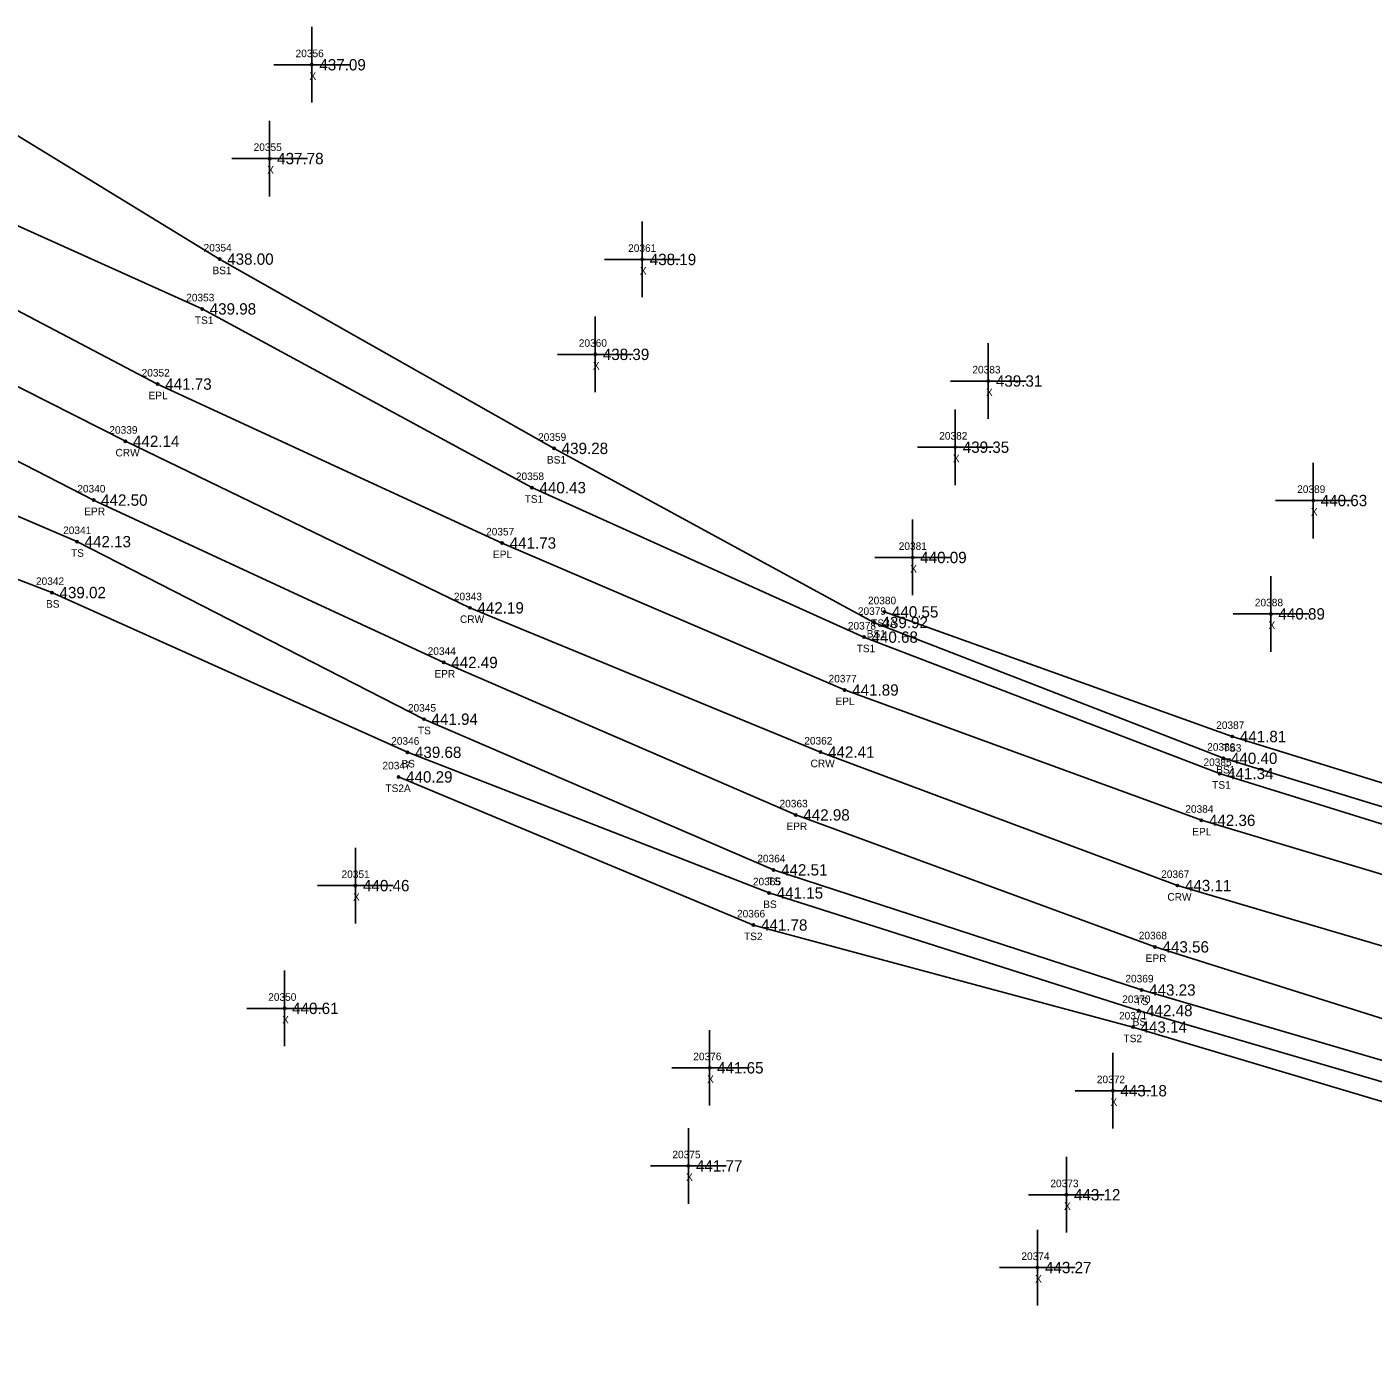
# Model space of a CAD drawing. Extents: x 1810114 to 1811498, y 790790 to 791824.
# Drawn here: x 1810834.7 to 1811012.6, y 791129.6 to 791306.9 of the extents above; entities that cross this region are included whole.
import ezdxf

# ---------------------------------------------------------------- set-up
doc = ezdxf.new("R2010")
doc.units = 0
for name, color, linetype in [('RD_DTM_BkLn1', 7, 'Continuous'), ('RD_DTM_BkLn2', 7, 'Continuous'), ('RD_DTM_BkLn_txCode', 7, 'Continuous'), ('RD_EX_Misc', 7, 'Continuous'), ('RD_EX_Misc_txCode', 7, 'Continuous'), ('RD_EX_Road', 7, 'Continuous'), ('RD_EX_Road_txCode', 7, 'Continuous'), ('RD_EX_TX_Misc_ELEV', 7, 'Continuous'), ('RD_EX_TX_Road_ELEV', 7, 'Continuous'), ('RD_HC_Survey_ELEV', 7, 'Continuous'), ('RD_HC_Survey_txCode', 7, 'Continuous'), ('RD_SMD_Locator', 7, 'Continuous')]:
    doc.layers.add(name, color=color, linetype=linetype)

msp = doc.modelspace()

# ---------------------------------------------------------------- linework, layer by layer
at = {"layer": 'RD_DTM_BkLn1'}
msp.add_lwpolyline([(1810803.51, 791274.51), (1810847.74, 791252.12), (1810893.26, 791230.1), (1810939.59, 791211.03), (1810986.75, 791193.39), (1811034.36, 791179.34), (1811083.17, 791167.31), (1811132.79, 791157.79), (1811182.67, 791151.51), (1811232.87, 791147.29), (1811282.59, 791145.39), (1811332.65, 791144.69), (1811383.13, 791143.44), (1811433.19, 791141.72), (1811483.07, 791139)], dxfattribs=at)
at = {"layer": 'RD_DTM_BkLn2'}
for points in [[(1810797.71, 791296.87), (1810806.65, 791301.43), (1810818.39, 791301.77), (1810860.19, 791276.21), (1810904.39, 791251.18), (1810946.65, 791228.17), (1810992.83, 791210.21), (1811039.32, 791196), (1811086.62, 791185.05), (1811136.39, 791175.32), (1811184.54, 791168.49), (1811233.77, 791164.27), (1811283.33, 791162.64), (1811288.69, 791162.37)], [(1810810.94, 791288.35), (1810813.31, 791289.84), (1810816.6, 791289.48), (1810819.25, 791288.81), (1810826.35, 791283.83), (1810857.88, 791269.62), (1810901.46, 791245.99), (1810945.33, 791226.23), (1810992.32, 791208.19), (1811038.63, 791193.8), (1811085.97, 791182.59), (1811135.79, 791172.72), (1811184.32, 791165.75), (1811233.45, 791162.61), (1811282.83, 791159.28), (1811288.11, 791158.81), (1811290.26, 791160.7), (1811291.15, 791162.18)], [(1810798.82, 791261.28), (1810799.43, 791259.17), (1810802.84, 791255.6), (1810808.45, 791252.93), (1810841.34, 791238.85), (1810887.19, 791215.38), (1810933.38, 791195.46), (1810982.02, 791179.58), (1811030.36, 791165.41), (1811080.28, 791153.78), (1811130.64, 791143.41), (1811141.73, 791142.21), (1811149.36, 791140.89), (1811151.79, 791139.84), (1811152.74, 791137.29)], [(1810783.34, 791255.23), (1810786.99, 791254.41), (1810790.75, 791251.26), (1810797.13, 791248.85), (1810804.71, 791244.89), (1810838.03, 791232.12), (1810885, 791211), (1810932.8, 791192.41), (1810981.62, 791176.86), (1811029.91, 791162.73), (1811079.91, 791150.39), (1811130.24, 791140.14), (1811146.59, 791138.06), (1811151.52, 791137.46)], [(1810948.03, 791229.57), (1810994, 791213.09), (1811040.42, 791198.74), (1811088.11, 791189.61), (1811135.95, 791180.55), (1811184.97, 791175.18), (1811234.87, 791170.81), (1811283.91, 791165.94), (1811289.01, 791164.74), (1811290.58, 791163.58), (1811291.15, 791162.18)], [(1810883.83, 791207.75), (1810930.73, 791188.17), (1810980.88, 791174.68), (1811028.83, 791160.33), (1811078.75, 791145.78), (1811129.26, 791134.04), (1811143.61, 791131.25), (1811148.31, 791132.87), (1811151.39, 791134.37), (1811152.74, 791137.29)]]:
    msp.add_lwpolyline(points, dxfattribs=at)
at = {"layer": 'RD_EX_Misc'}
for p, q in [((1810872.37, 791296.9), (1810872.37, 791306.9)), ((1810867.37, 791301.9), (1810877.37, 791301.9)), ((1810866.79, 791284.5), (1810866.79, 791294.5)), ((1810861.79, 791289.5), (1810871.79, 791289.5)), ((1810916.03, 791271.16), (1810916.03, 791281.16)), ((1810911.03, 791276.16), (1810921.03, 791276.16)), ((1810909.83, 791258.61), (1810909.83, 791268.61)), ((1810961.77, 791255.09), (1810961.77, 791265.09)), ((1810904.83, 791263.61), (1810914.83, 791263.61)), ((1810956.77, 791260.09), (1810966.77, 791260.09)), ((1810957.39, 791246.34), (1810957.39, 791256.34)), ((1810952.39, 791251.34), (1810962.39, 791251.34)), ((1811004.7, 791239.29), (1811004.7, 791249.29)), ((1810999.7, 791244.29), (1811009.7, 791244.29)), ((1810951.77, 791231.76), (1810951.77, 791241.76)), ((1810946.77, 791236.76), (1810956.77, 791236.76)), ((1810999.11, 791224.3), (1810999.11, 791234.3)), ((1810994.11, 791229.3), (1811004.11, 791229.3)), ((1810878.14, 791188.38), (1810878.14, 791198.38)), ((1810873.14, 791193.38), (1810883.14, 791193.38)), ((1810868.77, 791172.15), (1810868.77, 791182.15)), ((1810863.77, 791177.15), (1810873.77, 791177.15)), ((1810924.93, 791164.29), (1810924.93, 791174.29)), ((1810978.23, 791161.26), (1810978.23, 791171.26)), ((1810919.93, 791169.29), (1810929.93, 791169.29)), ((1810973.23, 791166.26), (1810983.23, 791166.26)), ((1810922.14, 791151.33), (1810922.14, 791161.33)), ((1810972.09, 791147.51), (1810972.09, 791157.51)), ((1810917.14, 791156.33), (1810927.14, 791156.33)), ((1810967.09, 791152.51), (1810977.09, 791152.51)), ((1810968.26, 791137.89), (1810968.26, 791147.89)), ((1810963.26, 791142.89), (1810973.26, 791142.89))]:
    msp.add_line(p, q, dxfattribs=at)
at = {"layer": 'RD_EX_Road'}
for points in [[(1810807.88, 791282.84), (1810852, 791259.68), (1810897.52, 791238.67), (1810942.78, 791219.24), (1810989.92, 791202.01), (1811037.03, 791187.9), (1811084.94, 791176.28), (1811134.78, 791167.28), (1811183.92, 791161.02), (1811232.9, 791156.58), (1811282.68, 791154.92), (1811285.25, 791154.67), (1811313.54, 791153.96), (1811332.83, 791153.68), (1811383.78, 791152.53), (1811433.81, 791151.61), (1811483.97, 791148.18)], [(1810799.46, 791266.97), (1810843.53, 791244.35), (1810889.8, 791222.88), (1810936.32, 791202.72), (1810983.79, 791185.28), (1811031.51, 791170.21), (1811081.62, 791158.02), (1811131.99, 791148.92), (1811148.3, 791146.24), (1811177.02, 791142.75), (1811182.52, 791142.23), (1811232.71, 791137.62), (1811281.86, 791136.25), (1811332.25, 791135.72), (1811383.92, 791134.19), (1811422.24, 791132.82), (1811433.21, 791132.2), (1811452.43, 791131.25), (1811482.29, 791129.59)]]:
    msp.add_lwpolyline(points, dxfattribs=at)
at = {"layer": 'RD_SMD_Locator'}
for centre in [(1810872.37, 791301.9), (1810866.79, 791289.5), (1810860.19, 791276.21), (1810916.03, 791276.16), (1810857.88, 791269.62), (1810909.83, 791263.61), (1810852, 791259.68), (1810961.77, 791260.09), (1810847.74, 791252.12), (1810904.39, 791251.18), (1810957.39, 791251.34), (1810901.46, 791245.99), (1810843.53, 791244.35), (1811004.7, 791244.29), (1810841.34, 791238.85), (1810897.52, 791238.67), (1810951.77, 791236.76), (1810838.03, 791232.12), (1810893.26, 791230.1), (1810948.03, 791229.57), (1810999.11, 791229.3), (1810946.65, 791228.17), (1810945.33, 791226.23), (1810889.8, 791222.88), (1810942.78, 791219.24), (1810887.19, 791215.38), (1810994, 791213.09), (1810885, 791211), (1810939.59, 791211.03), (1810992.83, 791210.21), (1810883.83, 791207.75), (1810992.32, 791208.19), (1810936.32, 791202.72), (1810989.92, 791202.01), (1810933.38, 791195.46), (1810878.14, 791193.38), (1810986.75, 791193.39), (1810932.8, 791192.41), (1810930.73, 791188.17), (1810983.79, 791185.28), (1810982.02, 791179.58), (1810868.77, 791177.15), (1810981.62, 791176.86), (1810980.88, 791174.68), (1810924.93, 791169.29), (1810978.23, 791166.26), (1810922.14, 791156.33), (1810972.09, 791152.51), (1810968.26, 791142.89)]:
    msp.add_circle(centre, 0.15, dxfattribs=at)

# ---------------------------------------------------------------- texts
at = {"layer": 'RD_DTM_BkLn_txCode'}
for s, p in [('20354', (1810858.07, 791277.21)), ('BS1', (1810859.24, 791274.21)), ('20353', (1810855.77, 791270.62)), ('TS1', (1810856.92, 791267.62)), ('20359', (1810902.27, 791252.18)), ('BS1', (1810903.44, 791249.18)), ('20358', (1810899.34, 791246.99)), ('TS1', (1810900.5, 791243.99)), ('20341', (1810839.51, 791239.85)), ('TS', (1810840.55, 791236.85)), ('20342', (1810835.92, 791233.12)), ('BS', (1810837.25, 791230.12)), ('20380', (1810945.87, 791230.57)), ('20379', (1810944.53, 791229.17)), ('20378', (1810943.21, 791227.23)), ('BS1', (1810945.7, 791226.17)), ('TS3A', (1810946.29, 791227.57)), ('TS1', (1810944.37, 791224.23)), ('20345', (1810885.07, 791216.38)), ('TS', (1810886.39, 791213.38)), ('20387', (1810991.88, 791214.09)), ('20346', (1810882.86, 791212)), ('20386', (1810990.69, 791211.21)), ('TS3', (1810992.76, 791211.09)), ('20347', (1810881.71, 791208.75)), ('BS', (1810884.22, 791209)), ('20385', (1810990.2, 791209.19)), ('BS1', (1810991.88, 791208.21)), ('TS2A', (1810882.1, 791205.75)), ('TS1', (1810991.35, 791206.19)), ('20364', (1810931.24, 791196.46)), ('20365', (1810930.66, 791193.41)), ('TS', (1810932.59, 791193.46)), ('BS', (1810932.02, 791190.41)), ('20366', (1810928.56, 791189.17)), ('TS2', (1810929.48, 791186.17)), ('20369', (1810979.88, 791180.58)), ('20370', (1810979.47, 791177.86)), ('TS', (1810981.23, 791177.58)), ('20371', (1810979.04, 791175.68)), ('BS', (1810980.84, 791174.86)), ('TS2', (1810979.63, 791172.68))]:
    msp.add_text(s, height=1, dxfattribs=at).set_placement(p)
at = {"layer": 'RD_EX_Misc_txCode'}
for s, p in [('20356', (1810870.23, 791302.9)), ('X', (1810872.06, 791299.9)), ('20355', (1810864.68, 791290.5)), ('X', (1810866.48, 791287.5)), ('20361', (1810914.17, 791277.16)), ('X', (1810915.72, 791274.16)), ('20360', (1810907.65, 791264.61)), ('X', (1810909.51, 791261.61)), ('20383', (1810959.66, 791261.09)), ('X', (1810961.46, 791258.09)), ('20382', (1810955.28, 791252.34)), ('X', (1810957.08, 791249.34)), ('20389', (1811002.58, 791245.29)), ('X', (1811004.39, 791242.29)), ('20381', (1810949.93, 791237.76)), ('X', (1810951.45, 791234.76)), ('20388', (1810996.99, 791230.3)), ('X', (1810998.79, 791227.3)), ('20351', (1810876.3, 791194.38)), ('X', (1810877.82, 791191.38)), ('20350', (1810866.61, 791178.15)), ('X', (1810868.45, 791175.15)), ('20376', (1810922.78, 791170.29)), ('X', (1810924.61, 791167.29)), ('20372', (1810976.11, 791167.26)), ('X', (1810977.91, 791164.26)), ('20375', (1810920.02, 791157.33)), ('X', (1810921.83, 791154.33)), ('20373', (1810969.97, 791153.51)), ('X', (1810971.77, 791150.51)), ('20374', (1810966.14, 791143.89)), ('X', (1810967.95, 791140.89))]:
    msp.add_text(s, height=1, dxfattribs=at).set_placement(p)
at = {"layer": 'RD_EX_Road_txCode'}
for s, p in [('20352', (1810849.88, 791260.68)), ('EPL', (1810850.8, 791257.68)), ('20340', (1810841.38, 791245.35)), ('EPR', (1810842.3, 791242.35)), ('20357', (1810895.4, 791239.67)), ('EPL', (1810896.31, 791236.67)), ('20344', (1810887.68, 791223.88)), ('EPR', (1810888.57, 791220.88)), ('20377', (1810940.66, 791220.24)), ('EPL', (1810941.57, 791217.24)), ('20363', (1810934.18, 791203.72)), ('20384', (1810987.8, 791203.01)), ('EPR', (1810935.09, 791200.72)), ('EPL', (1810988.72, 791200.01)), ('20368', (1810981.65, 791186.28)), ('EPR', (1810982.56, 791183.28))]:
    msp.add_text(s, height=1, dxfattribs=at).set_placement(p)
at = {"layer": 'RD_EX_TX_Misc_ELEV'}
for s, p in [('437.09', (1810873.37, 791301.15)), ('437.78', (1810867.79, 791288.75)), ('438.00', (1810861.19, 791275.46)), ('438.19', (1810917.03, 791275.41)), ('439.98', (1810858.88, 791268.87)), ('438.39', (1810910.83, 791262.86)), ('439.31', (1810962.77, 791259.34)), ('439.28', (1810905.39, 791250.43)), ('439.35', (1810958.39, 791250.59)), ('440.43', (1810902.46, 791245.24)), ('440.63', (1811005.7, 791243.54)), ('442.13', (1810842.34, 791238.1)), ('440.09', (1810952.77, 791236.01)), ('439.02', (1810839.03, 791231.37)), ('439.92', (1810947.65, 791227.42)), ('440.55', (1810949.03, 791228.82)), ('440.89', (1811000.11, 791228.55)), ('440.68', (1810946.33, 791225.48)), ('441.94', (1810888.19, 791214.63)), ('441.81', (1810995, 791212.34)), ('439.68', (1810886, 791210.25)), ('440.40', (1810993.83, 791209.46)), ('440.29', (1810884.83, 791207)), ('441.34', (1810993.32, 791207.44)), ('442.51', (1810934.38, 791194.71)), ('440.46', (1810879.14, 791192.63)), ('441.15', (1810933.8, 791191.66)), ('441.78', (1810931.73, 791187.42)), ('443.23', (1810983.02, 791178.83)), ('440.61', (1810869.77, 791176.4)), ('442.48', (1810982.62, 791176.11)), ('443.14', (1810981.88, 791173.93)), ('441.65', (1810925.93, 791168.54)), ('443.18', (1810979.23, 791165.51)), ('441.77', (1810923.14, 791155.58)), ('443.12', (1810973.09, 791151.76)), ('443.27', (1810969.26, 791142.14))]:
    msp.add_text(s, height=1.5, dxfattribs=at).set_placement(p)
at = {"layer": 'RD_EX_TX_Road_ELEV'}
for s, p in [('441.73', (1810853, 791258.93)), ('442.50', (1810844.53, 791243.6)), ('441.73', (1810898.52, 791237.92)), ('442.49', (1810890.8, 791222.13)), ('441.89', (1810943.78, 791218.49)), ('442.98', (1810937.32, 791201.97)), ('442.36', (1810990.92, 791201.26)), ('443.56', (1810984.79, 791184.53))]:
    msp.add_text(s, height=1.5, dxfattribs=at).set_placement(p)
at = {"layer": 'RD_HC_Survey_ELEV'}
for s, p in [('442.14', (1810848.74, 791251.37)), ('442.19', (1810894.26, 791229.35)), ('442.41', (1810940.59, 791210.28)), ('443.11', (1810987.75, 791192.64))]:
    msp.add_text(s, height=1.5, dxfattribs=at).set_placement(p)
at = {"layer": 'RD_HC_Survey_txCode'}
for s, p in [('20339', (1810845.62, 791253.12)), ('CRW', (1810846.43, 791250.12)), ('20343', (1810891.14, 791231.1)), ('CRW', (1810891.95, 791228.1)), ('20362', (1810937.45, 791212.03)), ('CRW', (1810938.28, 791209.03)), ('20367', (1810984.61, 791194.39)), ('CRW', (1810985.43, 791191.39))]:
    msp.add_text(s, height=1, dxfattribs=at).set_placement(p)

doc.saveas('drawing.dxf')
